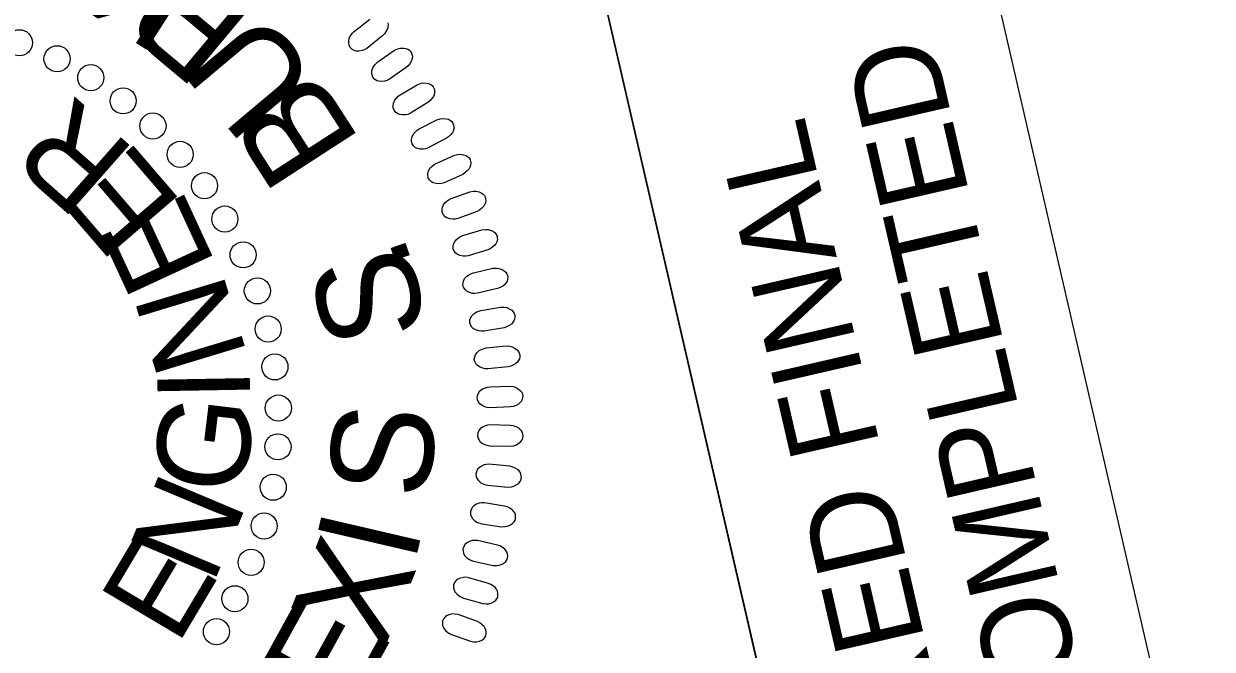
# Model space of a CAD drawing. Extents: x 480532 to 481977, y 491295 to 493182.
# Drawn here: x 480676.5 to 480749.4, y 492883.6 to 492921.9 of the extents above; entities that cross this region are included whole.
import ezdxf

# ---------------------------------------------------------------- set-up
doc = ezdxf.new("R2010")
doc.units = 0
for name, color, linetype in [('Sheet PE Seal Cell', 7, 'Continuous'), ('Sheet Plan CELL', 7, 'Continuous'), ('Sheet Sticker Exception Certification CELL', 7, 'Continuous'), ('Sheet Sticker Incomplete CELL', 7, 'Continuous')]:
    doc.layers.add(name, color=color, linetype=linetype)

msp = doc.modelspace()

# ---------------------------------------------------------------- linework, layer by layer
at = {"layer": 'Sheet PE Seal Cell'}
msp.add_lwpolyline([(480698.849, 492921.962), (480698.867, 492921.843), (480698.853, 492921.699), (480698.828, 492921.603), (480698.752, 492921.457), (480698.647, 492921.299), (480698.536, 492921.183), (480697.552, 492920.401), (480697.405, 492920.314), (480697.267, 492920.263), (480697.087, 492920.235), (480696.908, 492920.237), (480696.785, 492920.264), (480696.641, 492920.35), (480696.533, 492920.456), (480696.472, 492920.598), (480696.447, 492920.711), (480696.446, 492920.872), (480696.505, 492921.071), (480696.605, 492921.235), (480696.689, 492921.338), (480696.781, 492921.43), (480697.746, 492922.188)], dxfattribs=at)
for points in [[(480698.241, 492919.583), (480699.251, 492920.279), (480699.453, 492920.372), (480699.597, 492920.408), (480699.801, 492920.412), (480699.946, 492920.395), (480700.075, 492920.347), (480700.168, 492920.284), (480700.248, 492920.203), (480700.294, 492920.099), (480700.338, 492919.984), (480700.348, 492919.864), (480700.325, 492919.721), (480700.293, 492919.626), (480700.208, 492919.486), (480700.095, 492919.335), (480699.976, 492919.226), (480698.945, 492918.507), (480698.793, 492918.43), (480698.653, 492918.387), (480698.47, 492918.37), (480698.292, 492918.383), (480698.171, 492918.419), (480698.032, 492918.513), (480697.931, 492918.626), (480697.879, 492918.771), (480697.861, 492918.886), (480697.871, 492919.047), (480697.943, 492919.241), (480698.052, 492919.399), (480698.142, 492919.496)], [(480699.592, 492917.542), (480700.644, 492918.173), (480700.851, 492918.254), (480700.998, 492918.281), (480701.202, 492918.272), (480701.345, 492918.245), (480701.472, 492918.19), (480701.56, 492918.121), (480701.634, 492918.034), (480701.675, 492917.929), (480701.711, 492917.811), (480701.713, 492917.69), (480701.681, 492917.549), (480701.644, 492917.457), (480701.55, 492917.322), (480701.427, 492917.178), (480701.302, 492917.077), (480700.228, 492916.424), (480700.071, 492916.356), (480699.929, 492916.323), (480699.746, 492916.318), (480699.569, 492916.342), (480699.45, 492916.385), (480699.317, 492916.488), (480699.224, 492916.606), (480699.181, 492916.754), (480699.17, 492916.871), (480699.189, 492917.031), (480699.274, 492917.22), (480699.394, 492917.37), (480699.489, 492917.463)], [(480700.761, 492915.459), (480701.851, 492916.023), (480702.063, 492916.091), (480702.211, 492916.109), (480702.413, 492916.087), (480702.555, 492916.051), (480702.678, 492915.988), (480702.761, 492915.914), (480702.83, 492915.823), (480702.864, 492915.715), (480702.893, 492915.595), (480702.888, 492915.474), (480702.847, 492915.335), (480702.804, 492915.246), (480702.702, 492915.117), (480702.57, 492914.982), (480702.438, 492914.888), (480701.326, 492914.304), (480701.165, 492914.246), (480701.021, 492914.222), (480700.837, 492914.228), (480700.662, 492914.263), (480700.546, 492914.313), (480700.421, 492914.425), (480700.335, 492914.549), (480700.302, 492914.7), (480700.298, 492914.816), (480700.327, 492914.974), (480700.424, 492915.158), (480700.552, 492915.301), (480700.653, 492915.387)], [(480701.799, 492913.353), (480702.922, 492913.847), (480703.138, 492913.902), (480703.287, 492913.91), (480703.487, 492913.876), (480703.627, 492913.831), (480703.745, 492913.76), (480703.824, 492913.681), (480703.887, 492913.586), (480703.913, 492913.475), (480703.935, 492913.354), (480703.922, 492913.234), (480703.873, 492913.098), (480703.824, 492913.011), (480703.714, 492912.89), (480703.574, 492912.762), (480703.437, 492912.677), (480702.29, 492912.164), (480702.126, 492912.116), (480701.98, 492912.101), (480701.798, 492912.119), (480701.625, 492912.165), (480701.512, 492912.222), (480701.395, 492912.342), (480701.316, 492912.471), (480701.293, 492912.623), (480701.296, 492912.739), (480701.336, 492912.896), (480701.443, 492913.073), (480701.581, 492913.208), (480701.687, 492913.287)], [(480702.719, 492911.189), (480703.871, 492911.612), (480704.089, 492911.653), (480704.239, 492911.652), (480704.437, 492911.605), (480704.573, 492911.552), (480704.687, 492911.474), (480704.76, 492911.39), (480704.818, 492911.291), (480704.837, 492911.179), (480704.851, 492911.056), (480704.831, 492910.938), (480704.773, 492910.805), (480704.719, 492910.721), (480704.601, 492910.606), (480704.454, 492910.488), (480704.312, 492910.412), (480703.134, 492909.972), (480702.968, 492909.935), (480702.821, 492909.929), (480702.64, 492909.958), (480702.471, 492910.015), (480702.362, 492910.079), (480702.252, 492910.206), (480702.182, 492910.34), (480702.168, 492910.493), (480702.179, 492910.609), (480702.228, 492910.762), (480702.346, 492910.932), (480702.492, 492911.058), (480702.603, 492911.13)], [(480703.44, 492908.928), (480704.616, 492909.277), (480704.836, 492909.304), (480704.985, 492909.294), (480705.18, 492909.235), (480705.313, 492909.173), (480705.421, 492909.088), (480705.489, 492909), (480705.54, 492908.897), (480705.552, 492908.785), (480705.558, 492908.661), (480705.531, 492908.544), (480705.465, 492908.415), (480705.406, 492908.335), (480705.281, 492908.228), (480705.126, 492908.119), (480704.98, 492908.053), (480703.777, 492907.687), (480703.608, 492907.66), (480703.462, 492907.664), (480703.283, 492907.704), (480703.117, 492907.772), (480703.013, 492907.842), (480702.911, 492907.975), (480702.85, 492908.113), (480702.845, 492908.268), (480702.863, 492908.382), (480702.922, 492908.532), (480703.051, 492908.695), (480703.204, 492908.811), (480703.319, 492908.877)], [(480704.09, 492906.649), (480705.286, 492906.924), (480705.508, 492906.936), (480705.656, 492906.917), (480705.847, 492906.846), (480705.975, 492906.775), (480706.078, 492906.684), (480706.14, 492906.592), (480706.185, 492906.486), (480706.191, 492906.373), (480706.188, 492906.249), (480706.154, 492906.134), (480706.08, 492906.009), (480706.015, 492905.933), (480705.885, 492905.834), (480705.723, 492905.736), (480705.573, 492905.678), (480704.35, 492905.389), (480704.18, 492905.373), (480704.034, 492905.385), (480703.858, 492905.437), (480703.697, 492905.515), (480703.597, 492905.592), (480703.504, 492905.731), (480703.451, 492905.873), (480703.456, 492906.027), (480703.481, 492906.14), (480703.549, 492906.287), (480703.688, 492906.441), (480703.848, 492906.547), (480703.968, 492906.605)], [(480704.549, 492904.34), (480705.76, 492904.539), (480705.982, 492904.538), (480706.129, 492904.509), (480706.314, 492904.426), (480706.439, 492904.348), (480706.535, 492904.25), (480706.592, 492904.154), (480706.629, 492904.045), (480706.627, 492903.932), (480706.618, 492903.81), (480706.576, 492903.697), (480706.494, 492903.577), (480706.425, 492903.505), (480706.289, 492903.414), (480706.121, 492903.326), (480705.967, 492903.278), (480704.729, 492903.066), (480704.558, 492903.061), (480704.413, 492903.082), (480704.241, 492903.145), (480704.085, 492903.232), (480703.99, 492903.316), (480703.906, 492903.461), (480703.862, 492903.605), (480703.877, 492903.759), (480703.909, 492903.87), (480703.987, 492904.012), (480704.135, 492904.157), (480704.301, 492904.254), (480704.424, 492904.303)], [(480704.877, 492902.037), (480706.098, 492902.16), (480706.32, 492902.145), (480706.464, 492902.107), (480706.644, 492902.013), (480706.763, 492901.927), (480706.854, 492901.823), (480706.904, 492901.723), (480706.935, 492901.613), (480706.926, 492901.5), (480706.909, 492901.378), (480706.86, 492901.268), (480706.77, 492901.154), (480706.697, 492901.086), (480706.555, 492901.004), (480706.383, 492900.927), (480706.226, 492900.888), (480704.977, 492900.755), (480704.806, 492900.76), (480704.662, 492900.791), (480704.495, 492900.864), (480704.344, 492900.961), (480704.256, 492901.05), (480704.18, 492901.2), (480704.145, 492901.347), (480704.17, 492901.5), (480704.209, 492901.609), (480704.295, 492901.746), (480704.452, 492901.881), (480704.624, 492901.967), (480704.75, 492902.009)], [(480705.091, 492899.658), (480706.317, 492899.704), (480706.537, 492899.675), (480706.679, 492899.628), (480706.853, 492899.523), (480706.966, 492899.43), (480707.05, 492899.321), (480707.094, 492899.218), (480707.118, 492899.106), (480707.102, 492898.994), (480707.077, 492898.873), (480707.021, 492898.766), (480706.925, 492898.658), (480706.848, 492898.595), (480706.701, 492898.522), (480706.524, 492898.456), (480706.365, 492898.427), (480705.11, 492898.372), (480704.939, 492898.388), (480704.798, 492898.428), (480704.635, 492898.511), (480704.492, 492898.618), (480704.408, 492898.712), (480704.343, 492898.867), (480704.317, 492899.016), (480704.352, 492899.166), (480704.397, 492899.273), (480704.491, 492899.404), (480704.657, 492899.529), (480704.834, 492899.604), (480704.962, 492899.638)], [(480705.115, 492896.049), (480706.341, 492896.018), (480706.56, 492896.05), (480706.702, 492896.099), (480706.875, 492896.207), (480706.987, 492896.301), (480707.069, 492896.411), (480707.112, 492896.515), (480707.134, 492896.627), (480707.117, 492896.739), (480707.09, 492896.86), (480707.034, 492896.965), (480706.936, 492897.072), (480706.858, 492897.135), (480706.71, 492897.205), (480706.532, 492897.27), (480706.373, 492897.296), (480705.117, 492897.335), (480704.947, 492897.317), (480704.806, 492897.275), (480704.644, 492897.19), (480704.502, 492897.081), (480704.42, 492896.986), (480704.356, 492896.83), (480704.333, 492896.682), (480704.369, 492896.531), (480704.416, 492896.425), (480704.512, 492896.296), (480704.679, 492896.172), (480704.857, 492896.1), (480704.985, 492896.067)], [(480704.983, 492893.625), (480706.205, 492893.517), (480706.427, 492893.535), (480706.571, 492893.575), (480706.749, 492893.671), (480706.867, 492893.759), (480706.956, 492893.864), (480707.005, 492893.964), (480707.035, 492894.074), (480707.025, 492894.188), (480707.006, 492894.31), (480706.956, 492894.419), (480706.865, 492894.532), (480706.791, 492894.598), (480706.647, 492894.679), (480706.474, 492894.754), (480706.317, 492894.791), (480705.066, 492894.908), (480704.895, 492894.901), (480704.752, 492894.868), (480704.586, 492894.793), (480704.437, 492894.694), (480704.348, 492894.603), (480704.275, 492894.453), (480704.242, 492894.305), (480704.269, 492894.153), (480704.31, 492894.044), (480704.397, 492893.909), (480704.555, 492893.775), (480704.729, 492893.692), (480704.855, 492893.651)], [(480704.6, 492891.27), (480705.813, 492891.086), (480706.036, 492891.089), (480706.181, 492891.12), (480706.366, 492891.206), (480706.489, 492891.285), (480706.584, 492891.384), (480706.64, 492891.481), (480706.676, 492891.59), (480706.673, 492891.703), (480706.662, 492891.826), (480706.619, 492891.939), (480706.535, 492892.057), (480706.466, 492892.128), (480706.328, 492892.217), (480706.159, 492892.303), (480706.005, 492892.35), (480704.764, 492892.545), (480704.593, 492892.549), (480704.448, 492892.525), (480704.277, 492892.461), (480704.122, 492892.371), (480704.028, 492892.286), (480703.945, 492892.14), (480703.903, 492891.995), (480703.921, 492891.842), (480703.955, 492891.731), (480704.034, 492891.59), (480704.183, 492891.447), (480704.351, 492891.353), (480704.474, 492891.304)], [(480704.095, 492888.97), (480705.294, 492888.71), (480705.516, 492888.701), (480705.664, 492888.722), (480705.854, 492888.795), (480705.982, 492888.867), (480706.083, 492888.96), (480706.144, 492889.053), (480706.187, 492889.159), (480706.191, 492889.273), (480706.188, 492889.396), (480706.152, 492889.511), (480706.076, 492889.635), (480706.011, 492889.71), (480705.879, 492889.807), (480705.716, 492889.904), (480705.565, 492889.96), (480704.339, 492890.233), (480704.168, 492890.247), (480704.022, 492890.232), (480703.847, 492890.179), (480703.687, 492890.099), (480703.589, 492890.021), (480703.497, 492889.88), (480703.445, 492889.738), (480703.453, 492889.584), (480703.48, 492889.471), (480703.55, 492889.326), (480703.69, 492889.173), (480703.852, 492889.069), (480703.972, 492889.013)], [(480703.48, 492886.715), (480704.66, 492886.38), (480704.881, 492886.356), (480705.03, 492886.368), (480705.224, 492886.43), (480705.356, 492886.493), (480705.463, 492886.58), (480705.53, 492886.669), (480705.58, 492886.772), (480705.591, 492886.885), (480705.595, 492887.008), (480705.567, 492887.125), (480705.498, 492887.253), (480705.439, 492887.332), (480705.313, 492887.438), (480705.156, 492887.545), (480705.009, 492887.61), (480703.802, 492887.96), (480703.633, 492887.984), (480703.486, 492887.979), (480703.308, 492887.937), (480703.143, 492887.867), (480703.04, 492887.795), (480702.94, 492887.661), (480702.88, 492887.522), (480702.877, 492887.368), (480702.897, 492887.253), (480702.958, 492887.104), (480703.089, 492886.943), (480703.243, 492886.828), (480703.359, 492886.764)], [(480702.748, 492884.476), (480703.906, 492884.068), (480704.125, 492884.029), (480704.274, 492884.032), (480704.472, 492884.081), (480704.607, 492884.137), (480704.719, 492884.216), (480704.792, 492884.301), (480704.848, 492884.401), (480704.867, 492884.513), (480704.879, 492884.636), (480704.857, 492884.754), (480704.797, 492884.886), (480704.742, 492884.969), (480704.624, 492885.082), (480704.474, 492885.198), (480704.331, 492885.273), (480703.149, 492885.698), (480702.981, 492885.733), (480702.835, 492885.737), (480702.654, 492885.705), (480702.485, 492885.647), (480702.378, 492885.581), (480702.268, 492885.453), (480702.201, 492885.319), (480702.189, 492885.164), (480702.201, 492885.049), (480702.252, 492884.896), (480702.372, 492884.727), (480702.52, 492884.604), (480702.631, 492884.532)]]:
    msp.add_lwpolyline(points, close=True, dxfattribs=at)
for centre in [(480676.263, 492920.741), (480678.573, 492919.761), (480680.638, 492918.602), (480682.624, 492917.183), (480684.45, 492915.642), (480686.118, 492913.902), (480687.61, 492911.981), (480688.857, 492909.939), (480689.975, 492907.746), (480690.851, 492905.537), (480691.512, 492903.197), (480691.923, 492900.881), (480692.136, 492898.356), (480692.111, 492895.981), (480691.822, 492893.504), (480691.265, 492891.129), (480690.469, 492888.903), (480689.471, 492886.671), (480688.341, 492884.654)]:
    msp.add_circle(centre, 0.801, dxfattribs=at)
at = {"layer": 'Sheet Plan CELL'}
for points in [[(481918.067, 491698.303), (480894.93, 491462.423), (480602.878, 492729.179), (480749.103, 492762.9), (480704.18, 492957.828), (481581.119, 493159.981)], [(480617.018, 492835.113), (480594.546, 492932.542), (480704.18, 492957.828), (480726.655, 492860.387)]]:
    msp.add_lwpolyline(points, close=True, dxfattribs=at)
at = {"layer": 'Sheet Sticker Exception Certification CELL'}
for p, q in [((480727.068, 492963.104), (480772.002, 492768.179)), ((480727.068, 492963.104), (480772.002, 492768.179)), ((480749.103, 492762.9), (480704.168, 492957.825)), ((480749.103, 492762.9), (480704.168, 492957.825))]:
    msp.add_line(p, q, dxfattribs=at)

# ---------------------------------------------------------------- texts
at = {"layer": 'Sheet PE Seal Cell'}
for s, height, rotation, p in [('K', 6.236, 147.40372, (480687.998, 492925.197)), ('R', 6.236, 140.12869, (480691.055, 492922.586)), ('U', 6.236, 130.02884, (480694.756, 492918.406)), ('B', 6.236, 122.912, (480697.245, 492914.65)), ('R', 5.669, 138.64468, (480683.481, 492914.074)), ('E', 5.669, 130.70488, (480686.34, 492910.853)), ('E', 5.669, 114.82528, (480688.348, 492907.139)), ('.', 6.236, 109.20939, (480700.439, 492907.011)), ('S', 6.236, 102.36373, (480701.298, 492903.064)), ('N', 5.669, 106.88549, (480690.253, 492901.577)), ('I', 5.669, 91.00589, (480690.411, 492898.788)), ('G', 5.669, 83.06609, (480690.029, 492892.924)), ('S', 6.236, 83.76853, (480701.308, 492892.679)), ('N', 5.669, 67.1865, (480688.109, 492887.459)), ('I', 6.236, 76.92287, (480700.479, 492888.737)), ('E', 5.669, 59.2467, (480685.933, 492883.74)), ('X', 6.236, 67.97555, (480698.564, 492883.422)), ('E', 6.236, 61.12989, (480696.431, 492879.439))]:
    msp.add_text(s, height=height, rotation=rotation, dxfattribs=at).set_placement(p)
at = {"layer": 'Sheet Sticker Exception Certification CELL'}
for s, p in [('UNLESS ALL SIGNATURES COMPLETED', (480764.165, 492782.792)), ('UNLESS ALL SIGNATURES COMPLETED', (480764.165, 492782.792)), ('DOCUMENT NOT CONSIDERED FINAL', (480754.45, 492785.756)), ('DOCUMENT NOT CONSIDERED FINAL', (480754.45, 492785.756))]:
    msp.add_text(s, height=5.5, rotation=102.98112, dxfattribs=at).set_placement(p)
at = {"layer": 'Sheet Sticker Incomplete CELL'}
msp.add_text('DO NOT USE FOR R/W ACQUISITION', height=5.76, rotation=102.98112, dxfattribs=at).set_placement((480680.972, 492786.948))

doc.saveas('drawing.dxf')
